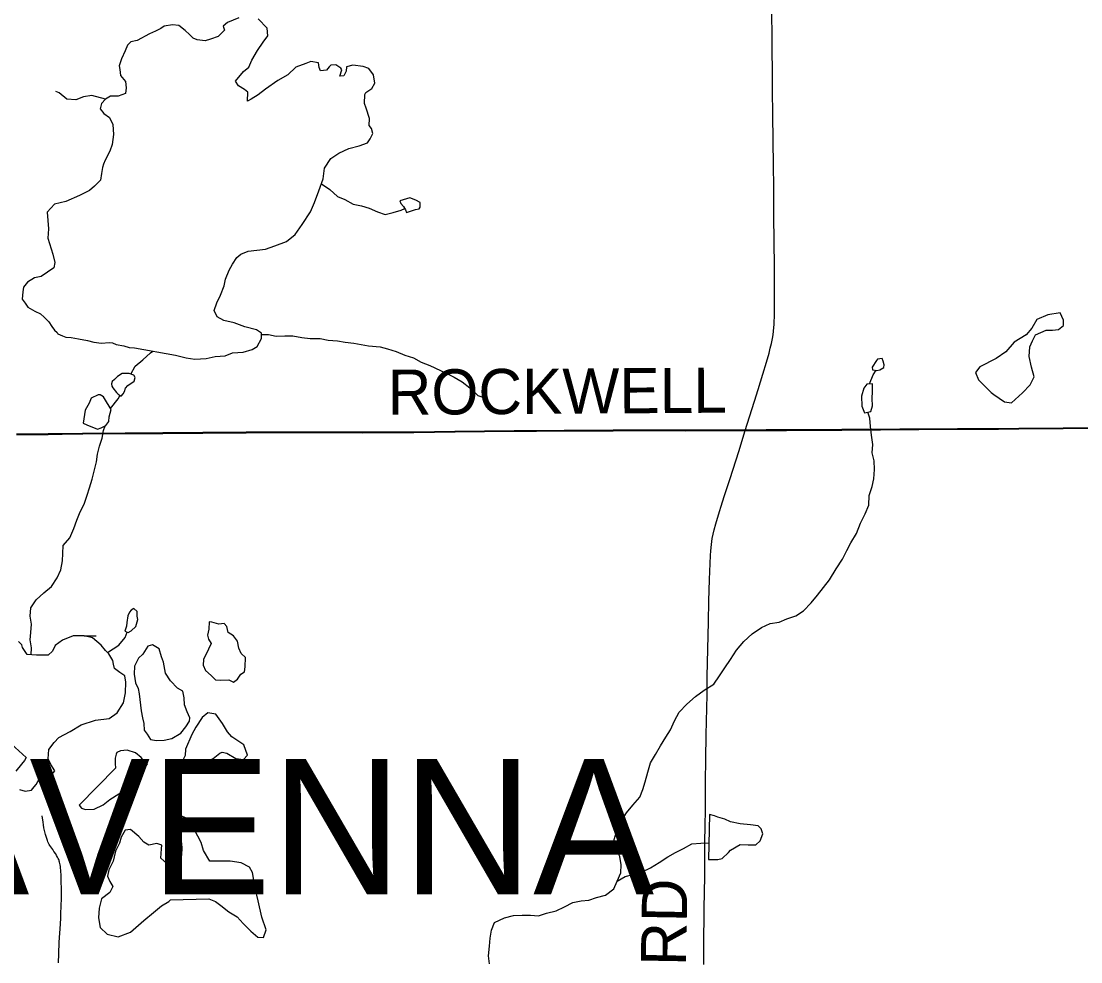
# Model space of a CAD drawing. Extents: x 0 to 34, y 0 to 22.
# Drawn here: x 14.299 to 15.63, y 14.945 to 16.128 of the extents above; entities that cross this region are included whole.
import ezdxf

# ---------------------------------------------------------------- set-up
doc = ezdxf.new("R2010")
doc.units = 0
for name, color, linetype in [('GM_X_Corporation', 7, 'Continuous'), ('GM_X_County_Road', 7, 'Continuous'), ('GM_X_County_Road_Text', 7, 'Continuous'), ('GM_X_Minor_Lake', 7, 'Continuous'), ('GM_X_Minor_River', 7, 'Continuous'), ('GM_X_Township_Road', 7, 'Continuous'), ('GM_X_Township_Text', 7, 'Continuous')]:
    doc.layers.add(name, color=color, linetype=linetype)

msp = doc.modelspace()

# ---------------------------------------------------------------- linework, layer by layer
at = {"layer": 'GM_X_Corporation'}
for points in [[(15.7195, 15.617), (15.5524, 15.6155), (15.5269, 15.6153), (15.4753, 15.6152), (15.3299, 15.6141), (15.3088, 15.6139), (15.2827, 15.614), (15.2604, 15.6138), (15.235, 15.6138), (15.2084, 15.6136), (15.172, 15.6134), (15.1329, 15.6134), (15.118, 15.6134), (15.0752, 15.6136), (15.0424, 15.6134), (14.9809, 15.6131), (14.9461, 15.6128), (14.9181, 15.6126), (14.8436, 15.6117), (14.792, 15.6111), (14.7634, 15.611), (14.7274, 15.6109), (14.7019, 15.6109), (14.6523, 15.6109), (14.6393, 15.6109), (14.6208, 15.611), (14.5813, 15.6109), (14.5268, 15.6104), (14.492, 15.61), (14.4765, 15.6099), (14.4473, 15.6097), (14.4292, 15.6096), (14.3758, 15.6093), (14.3497, 15.6089), (14.3323, 15.6087), (14.2926, 15.6084)], [(14.2926, 15.6084), (14.3323, 15.6087), (14.3497, 15.6089), (14.3758, 15.6093), (14.4292, 15.6096), (14.4473, 15.6097), (14.4765, 15.6099), (14.492, 15.61), (14.5268, 15.6104), (14.5813, 15.6109), (14.6208, 15.611), (14.6393, 15.6109), (14.6523, 15.6109), (14.7019, 15.6109), (14.7274, 15.6109), (14.7634, 15.611), (14.792, 15.6111), (14.8436, 15.6117), (14.9181, 15.6126), (14.9461, 15.6128), (14.9809, 15.6131), (15.0424, 15.6134), (15.0752, 15.6136), (15.118, 15.6134), (15.1329, 15.6134), (15.172, 15.6134), (15.2084, 15.6136), (15.235, 15.6138), (15.2604, 15.6138), (15.2827, 15.614), (15.3088, 15.6139), (15.3299, 15.6141), (15.4753, 15.6152), (15.5269, 15.6153), (15.5524, 15.6155), (15.7195, 15.617)]]:
    msp.add_lwpolyline(points, dxfattribs=at)
at = {"layer": 'GM_X_County_Road'}
for points in [[(15.2086, 15.6131), (15.2141, 15.6303), (15.2203, 15.6499), (15.2248, 15.6645), (15.2308, 15.6839), (15.2353, 15.6991), (15.2385, 15.7103), (15.2401, 15.7164), (15.2416, 15.7225), (15.2428, 15.7288), (15.2435, 15.7334), (15.2441, 15.738), (15.2446, 15.7426), (15.2448, 15.7465), (15.2453, 15.7598), (15.2454, 15.7669), (15.2454, 15.7757), (15.2454, 15.7911), (15.2453, 15.8193), (15.2445, 15.8826), (15.2444, 15.9209), (15.2441, 15.9449), (15.2436, 15.9788), (15.2433, 16.0086), (15.2431, 16.0193), (15.243, 16.0319), (15.2427, 16.0626), (15.2425, 16.0936), (15.242, 16.153)], [(14.2928, 15.6079), (14.3325, 15.6082), (14.3499, 15.6084), (14.376, 15.6087), (14.4295, 15.6091), (14.4475, 15.6092), (14.4767, 15.6094), (14.4922, 15.6095), (14.527, 15.6098), (14.5815, 15.6103), (14.621, 15.6104), (14.6395, 15.6104), (14.6525, 15.6104), (14.7021, 15.6104), (14.7276, 15.6103), (14.7636, 15.6104), (14.7922, 15.6105), (14.8438, 15.6112), (14.9183, 15.612), (14.9463, 15.6122), (14.9811, 15.6125), (15.0426, 15.6128), (15.0754, 15.613), (15.1182, 15.6129), (15.1331, 15.6128), (15.1722, 15.6129), (15.2086, 15.6131)], [(15.1564, 14.9415), (15.1565, 14.9632), (15.1571, 15.0123), (15.1576, 15.0521), (15.1578, 15.0806), (15.1579, 15.0931), (15.1584, 15.1179), (15.1585, 15.134), (15.1585, 15.152), (15.1586, 15.1632), (15.1588, 15.1713), (15.159, 15.1998), (15.1596, 15.2303), (15.1606, 15.2806), (15.1609, 15.3038), (15.1625, 15.3723), (15.163, 15.3983), (15.1637, 15.4256), (15.1645, 15.4456), (15.165, 15.456), (15.1655, 15.4618), (15.1662, 15.4695), (15.1672, 15.4772), (15.1683, 15.4828), (15.1695, 15.488), (15.1717, 15.4957), (15.1763, 15.5112), (15.1783, 15.5177), (15.1822, 15.5301), (15.1895, 15.5525), (15.2006, 15.5868), (15.2086, 15.6131)], [(15.2086, 15.6131), (15.2352, 15.6132), (15.2606, 15.6132), (15.2829, 15.6134), (15.309, 15.6134), (15.3301, 15.6135), (15.4755, 15.6146), (15.5271, 15.6148), (15.5526, 15.615), (15.7197, 15.6165), (15.7905, 15.6172), (15.849, 15.6177), (16.0069, 15.6183)]]:
    msp.add_lwpolyline(points, dxfattribs=at)
at = {"layer": 'GM_X_Minor_Lake'}
for p, q in [((14.7827, 15.887), (14.794, 15.8908)), ((14.4411, 15.7171), (14.4923, 15.7076)), ((15.3734, 15.7011), (15.3682, 15.6927)), ((15.5016, 15.6766), (15.5176, 15.6608)), ((15.5176, 15.6608), (15.5023, 15.6763)), ((14.4136, 15.6668), (14.4182, 15.6609)), ((15.3545, 15.6562), (15.3552, 15.6437)), ((14.381, 15.6203), (14.3946, 15.6147)), ((14.4324, 15.3799), (14.4313, 15.3715)), ((14.5338, 15.3382), (14.5275, 15.3249)), ((14.4468, 15.2818), (14.4493, 15.2606)), ((14.3458, 15.2268), (14.3601, 15.2345)), ((14.5131, 15.2307), (14.5049, 15.2125)), ((14.4375, 15.1638), (14.4573, 15.1939)), ((15.1637, 15.1303), (15.1623, 15.0734)), ((14.4863, 15.0227), (14.5344, 15.0242))]:
    msp.add_line(p, q, dxfattribs=at)
for points in [[(14.4923, 15.7076), (14.5059, 15.7043), (14.5169, 15.7029), (14.5309, 15.7034), (14.5423, 15.7061), (14.5548, 15.707), (14.5642, 15.7108), (14.5774, 15.7117), (14.5888, 15.7148), (14.5952, 15.7187), (14.6004, 15.7286), (14.6007, 15.7354), (14.5942, 15.7395), (14.5798, 15.7432), (14.5662, 15.7484), (14.5533, 15.7513), (14.5449, 15.7558), (14.5411, 15.7641), (14.5444, 15.7736), (14.5492, 15.7832), (14.5537, 15.7949), (14.5555, 15.8033), (14.56, 15.8147), (14.5641, 15.822), (14.5697, 15.8307), (14.5746, 15.8349), (14.584, 15.8384), (14.6056, 15.8412), (14.6173, 15.8451), (14.632, 15.8505), (14.6429, 15.8597), (14.6519, 15.8719), (14.662, 15.8879), (14.6672, 15.8997), (14.6727, 15.9146), (14.6779, 15.9294), (14.6797, 15.9431), (14.6879, 15.9549), (14.6977, 15.9618), (14.7102, 15.9676), (14.7234, 15.9711), (14.7336, 15.9746), (14.7373, 15.9799), (14.7407, 15.9864), (14.7387, 15.9928), (14.7361, 15.9966), (14.7364, 16.0053), (14.7321, 16.0182), (14.7302, 16.0242), (14.7305, 16.0356), (14.7316, 16.0379), (14.7391, 16.0429), (14.7432, 16.0497), (14.7412, 16.0603), (14.7355, 16.0683), (14.7283, 16.0709), (14.7154, 16.0723), (14.7075, 16.0703), (14.7068, 16.065), (14.7042, 16.0589), (14.6989, 16.0585), (14.7015, 16.0665), (14.7003, 16.0688), (14.6942, 16.0729), (14.6878, 16.0725), (14.6855, 16.0705), (14.6822, 16.0663), (14.6746, 16.0655), (14.673, 16.0697), (14.6722, 16.0754), (14.6624, 16.0772), (14.6564, 16.0745), (14.6439, 16.0698), (14.6338, 16.0603), (14.6209, 16.053), (14.6055, 16.0422), (14.5965, 16.0353), (14.5878, 16.0296), (14.5829, 16.0273), (14.5832, 16.0387), (14.5794, 16.042), (14.5718, 16.0465), (14.568, 16.0522), (14.5781, 16.0644), (14.5845, 16.0701), (14.5886, 16.0789), (14.5957, 16.0911), (14.6028, 16.1014), (14.6084, 16.1094), (14.6076, 16.1189), (14.5965, 16.1309)], [(14.5723, 16.1319), (14.5579, 16.1261), (14.5523, 16.1215), (14.5542, 16.1166), (14.546, 16.1085), (14.5365, 16.1051), (14.5297, 16.1031), (14.5199, 16.1045), (14.5149, 16.1064)], [(14.5149, 16.1064), (14.51, 16.1109), (14.5046, 16.1162), (14.4966, 16.1222), (14.4887, 16.1233), (14.4781, 16.1217), (14.474, 16.1186), (14.4672, 16.1151), (14.46, 16.1117), (14.4442, 16.1036), (14.4362, 16.1016), (14.4321, 16.0974), (14.4291, 16.0906), (14.4247, 16.0803), (14.4217, 16.0716), (14.4225, 16.067), (14.4233, 16.0594), (14.4298, 16.0519), (14.4306, 16.0439), (14.4296, 16.0367), (14.4205, 16.0336), (14.411, 16.0336), (14.4046, 16.0297), (14.3994, 16.0244), (14.3979, 16.0175), (14.4025, 16.0115), (14.4097, 16.0066), (14.4136, 15.9979), (14.4144, 15.9854), (14.413, 15.9725), (14.4101, 15.9641), (14.4041, 15.9531), (14.4019, 15.9481), (14.4008, 15.9436), (14.3993, 15.9364), (14.3982, 15.928), (14.3907, 15.9204), (14.3843, 15.915), (14.3719, 15.9085), (14.3545, 15.9008), (14.3406, 15.8976), (14.3312, 15.8877), (14.3329, 15.8665), (14.3322, 15.8551), (14.3384, 15.8346), (14.3408, 15.8244), (14.3397, 15.8176), (14.3235, 15.8068), (14.3152, 15.8049), (14.3065, 15.7995), (14.3013, 15.7934), (14.3006, 15.7873), (14.2999, 15.7782), (14.3037, 15.7733), (14.3068, 15.768), (14.3155, 15.7632), (14.3227, 15.7598), (14.3273, 15.7557), (14.3334, 15.7497), (14.3372, 15.744), (14.3403, 15.7391), (14.3437, 15.7361), (14.3445, 15.7346), (14.3506, 15.732), (14.3547, 15.7305), (14.3612, 15.7298), (14.3706, 15.7283), (14.382, 15.7261), (14.39, 15.7243), (14.3995, 15.7228), (14.4093, 15.7237), (14.4131, 15.7233), (14.418, 15.7211), (14.4275, 15.7193), (14.4343, 15.7174), (14.4411, 15.7171)], [(14.794, 15.8908), (14.7986, 15.8916), (14.8001, 15.8939), (14.8, 15.8996), (14.7947, 15.9026), (14.7871, 15.9056), (14.7746, 15.9017), (14.7758, 15.8983), (14.7792, 15.8949), (14.7815, 15.8907), (14.7827, 15.887)], [(15.6042, 15.7612), (15.5887, 15.7585), (15.5751, 15.7527), (15.5688, 15.7416), (15.5617, 15.7332), (15.5466, 15.724), (15.5361, 15.7118), (15.5241, 15.7037), (15.5033, 15.693), (15.4981, 15.6861), (15.5016, 15.6766)], [(15.5176, 15.6608), (15.521, 15.6582), (15.5343, 15.6492), (15.5434, 15.6478), (15.5569, 15.6604), (15.5667, 15.6703), (15.5719, 15.6806), (15.5684, 15.6927), (15.5653, 15.706), (15.5663, 15.7181), (15.5697, 15.7257), (15.5734, 15.7333), (15.587, 15.7391), (15.5949, 15.7392), (15.6021, 15.74), (15.6085, 15.745), (15.6085, 15.7518), (15.6042, 15.7612), (15.5887, 15.7585), (15.5751, 15.7527), (15.5688, 15.7416), (15.5617, 15.7332), (15.5466, 15.724), (15.5361, 15.7118), (15.5241, 15.7037), (15.5033, 15.693), (15.4981, 15.6861), (15.5016, 15.6766)], [(15.5176, 15.6608), (15.521, 15.6582), (15.5343, 15.6492), (15.5434, 15.6478), (15.5569, 15.6604), (15.5667, 15.6703), (15.5719, 15.6806), (15.5684, 15.6927), (15.5653, 15.706), (15.5663, 15.7181), (15.5697, 15.7257), (15.5734, 15.7333), (15.587, 15.7391), (15.5949, 15.7392), (15.6021, 15.74), (15.6085, 15.745), (15.6085, 15.7518), (15.6042, 15.7612)], [(15.3682, 15.6927), (15.3686, 15.6893), (15.3739, 15.6886), (15.3777, 15.6894), (15.3826, 15.6924), (15.3833, 15.6958), (15.3818, 15.7004), (15.3806, 15.7034), (15.3749, 15.7026), (15.3734, 15.7011)], [(14.4182, 15.6609), (14.4204, 15.6589), (14.4242, 15.6563), (14.4268, 15.659), (14.4283, 15.662), (14.4298, 15.6662), (14.4324, 15.6696), (14.4407, 15.675), (14.4418, 15.6796), (14.4403, 15.6826), (14.4342, 15.6848), (14.4255, 15.6847), (14.4195, 15.6809), (14.4157, 15.6771), (14.4127, 15.6748), (14.412, 15.6717), (14.4124, 15.6687), (14.4136, 15.6668)], [(15.3552, 15.6437), (15.3584, 15.6354), (15.3664, 15.6369), (15.3686, 15.6442), (15.3681, 15.6532), (15.3684, 15.662), (15.3684, 15.6718), (15.3616, 15.6714), (15.3578, 15.6664), (15.3545, 15.6562)], [(14.3946, 15.6147), (14.3992, 15.6163), (14.4048, 15.6194), (14.4085, 15.6243), (14.4093, 15.6304), (14.4104, 15.6349), (14.4115, 15.6395), (14.4092, 15.6437), (14.4057, 15.6489), (14.4019, 15.6554), (14.3977, 15.658), (14.3954, 15.658), (14.3867, 15.6537), (14.3841, 15.6473), (14.3789, 15.6385), (14.3764, 15.6222), (14.381, 15.6203)], [(14.4313, 15.3715), (14.431, 15.367), (14.4288, 15.3609), (14.433, 15.359), (14.4367, 15.3613), (14.4427, 15.3667), (14.4453, 15.3754), (14.4445, 15.3796), (14.4445, 15.3853), (14.4403, 15.3891), (14.4369, 15.3871), (14.4347, 15.3845), (14.4324, 15.3799)], [(14.5275, 15.3249), (14.5271, 15.3181), (14.5302, 15.3112), (14.5375, 15.3049), (14.5428, 15.2996), (14.5492, 15.2989), (14.5595, 15.2997), (14.5652, 15.2967), (14.5704, 15.3002), (14.5745, 15.3067), (14.5791, 15.3097), (14.5801, 15.3158), (14.5804, 15.3276), (14.5751, 15.3324), (14.572, 15.3392), (14.5704, 15.3483), (14.5655, 15.3547), (14.5586, 15.3592), (14.557, 15.3664), (14.5536, 15.3702), (14.5468, 15.3694), (14.5381, 15.372), (14.5347, 15.3723), (14.5344, 15.3632), (14.5325, 15.3556), (14.5341, 15.3507), (14.5375, 15.3451), (14.5338, 15.3382)], [(14.3601, 15.2345), (14.3741, 15.2429), (14.3918, 15.2488), (14.4092, 15.2508), (14.419, 15.2581), (14.4272, 15.2706), (14.4298, 15.2832), (14.43, 15.2965), (14.4288, 15.3044), (14.4224, 15.3089), (14.4159, 15.3138), (14.4147, 15.3191), (14.4136, 15.324), (14.4089, 15.3323), (14.4044, 15.3365), (14.399, 15.3429), (14.388, 15.3523), (14.3777, 15.3548), (14.3637, 15.3547), (14.3505, 15.3493), (14.3411, 15.3428), (14.3378, 15.3356), (14.3325, 15.3306), (14.3177, 15.3305), (14.306, 15.3315), (14.3003, 15.3402), (14.2995, 15.3436), (14.2953, 15.3478)], [(14.4493, 15.2606), (14.4512, 15.2519), (14.4528, 15.2447), (14.4532, 15.2363), (14.4567, 15.2311), (14.4609, 15.2246), (14.4685, 15.2232), (14.4783, 15.2236), (14.4878, 15.2256), (14.4991, 15.2325), (14.5054, 15.2405), (14.5099, 15.2474), (14.5106, 15.2516), (14.5072, 15.2591), (14.5037, 15.2682), (14.5032, 15.2769), (14.5017, 15.2852), (14.4948, 15.289), (14.4864, 15.2984), (14.4799, 15.3078), (14.4772, 15.3215), (14.4748, 15.3283), (14.4721, 15.3385), (14.4634, 15.3434), (14.4577, 15.3418), (14.4513, 15.3319), (14.4461, 15.3269), (14.4409, 15.3166), (14.4406, 15.3068), (14.4422, 15.2958), (14.4456, 15.2886), (14.4468, 15.2818)], [(14.5049, 15.2125), (14.5046, 15.2045), (14.5012, 15.1976), (14.5062, 15.1916), (14.5172, 15.1917), (14.527, 15.1944), (14.5398, 15.2006), (14.5481, 15.2071), (14.5511, 15.2086), (14.5572, 15.2072), (14.5682, 15.2004), (14.578, 15.1994), (14.5829, 15.2047), (14.5783, 15.2176), (14.5634, 15.2277), (14.5577, 15.2341), (14.5516, 15.2447), (14.5431, 15.2564), (14.5333, 15.2582), (14.5261, 15.2521), (14.5179, 15.2399), (14.5131, 15.2307)], [(14.2964, 15.1616), (14.3036, 15.1594), (14.3115, 15.1606), (14.3149, 15.1651), (14.3175, 15.1678), (14.3216, 15.1754), (14.3204, 15.1811), (14.3208, 15.186), (14.3337, 15.1778), (14.3393, 15.1831), (14.3408, 15.185), (14.3359, 15.193), (14.3324, 15.2001), (14.3334, 15.2119), (14.3398, 15.2207), (14.3458, 15.2268)], [(14.2865, 15.2188), (14.3048, 15.2018), (14.3029, 15.198), (14.2988, 15.1934), (14.2916, 15.1847)], [(14.4573, 15.1939), (14.4535, 15.1965), (14.4493, 15.2018), (14.4421, 15.2078), (14.4319, 15.2111), (14.4232, 15.2103), (14.4186, 15.208), (14.4179, 15.2061), (14.4168, 15.2008), (14.4165, 15.1943), (14.4169, 15.1883), (14.3715, 15.1417), (14.3745, 15.1383), (14.3795, 15.1364), (14.3904, 15.1369), (14.4014, 15.1423), (14.41, 15.1488), (14.4213, 15.1561), (14.4292, 15.1599), (14.4375, 15.1638)], [(14.5344, 15.0242), (14.5427, 15.0209), (14.5496, 15.0156), (14.5595, 15.0077), (14.5698, 15.0014), (14.5774, 14.9931), (14.5873, 14.9833), (14.5961, 14.9758), (14.6029, 14.9755), (14.6066, 14.985), (14.6008, 15.0009), (14.5965, 15.0217), (14.5926, 15.0376), (14.5894, 15.0573), (14.5855, 15.0641), (14.5749, 15.0693), (14.5613, 15.0715), (14.551, 15.0714), (14.5355, 15.0716), (14.5275, 15.0849), (14.5247, 15.0951), (14.5163, 15.1109), (14.5109, 15.1192), (14.5052, 15.126), (14.4968, 15.1297), (14.492, 15.1244), (14.4951, 15.113), (14.499, 15.1006), (14.5006, 15.0888), (14.4999, 15.079), (14.4943, 15.0725), (14.4814, 15.0686), (14.4742, 15.0753), (14.4748, 15.0871), (14.4752, 15.0917), (14.4691, 15.0935), (14.4589, 15.0915), (14.4528, 15.0953), (14.4463, 15.1024), (14.436, 15.1111), (14.4292, 15.1103), (14.4244, 15.1015), (14.4222, 15.0943), (14.417, 15.084), (14.4155, 15.0768), (14.414, 15.0715), (14.4088, 15.0604), (14.407, 15.0525), (14.4101, 15.046), (14.4139, 15.0396), (14.4098, 15.032), (14.3993, 15.0243), (14.3967, 15.0122), (14.3957, 15), (14.398, 14.9879), (14.4064, 14.9797), (14.4205, 14.9763), (14.4359, 14.9822), (14.4528, 14.9967), (14.4649, 15.007), (14.475, 15.0154), (14.4841, 15.0208), (14.4863, 15.0227)], [(15.1623, 15.0734), (15.174, 15.0735), (15.1797, 15.075), (15.1875, 15.0823), (15.1902, 15.0854), (15.2022, 15.0923), (15.2124, 15.092), (15.2219, 15.0921), (15.2272, 15.097), (15.2305, 15.1058), (15.2286, 15.1122), (15.2247, 15.116), (15.2153, 15.117), (15.202, 15.1184), (15.1899, 15.121), (15.1831, 15.1244), (15.1743, 15.127), (15.1698, 15.1284), (15.1637, 15.1303)]]:
    msp.add_lwpolyline(points, dxfattribs=at)
at = {"layer": 'GM_X_Minor_River'}
for points in [[(14.4046, 16.0297), (14.3872, 16.0345), (14.377, 16.0325), (14.3672, 16.029), (14.3558, 16.0297), (14.3463, 16.0376), (14.3421, 16.0395)], [(14.6758, 15.9233), (14.6863, 15.9162), (14.6959, 15.9072), (14.7054, 15.9034), (14.716, 15.8978), (14.7262, 15.8956), (14.7361, 15.8927), (14.7464, 15.8882), (14.7562, 15.8845), (14.7661, 15.8872), (14.7763, 15.8899), (14.7809, 15.892)], [(14.6006, 15.7338), (14.6094, 15.7336), (14.6189, 15.7317), (14.6299, 15.7322), (14.6401, 15.7319), (14.6511, 15.7301), (14.6617, 15.7286), (14.6742, 15.7287), (14.6844, 15.7265), (14.6962, 15.7259), (14.7056, 15.724), (14.7166, 15.723), (14.7352, 15.7193), (14.7496, 15.7183), (14.7591, 15.7157), (14.7697, 15.7124), (14.7807, 15.7079), (14.7917, 15.7046), (14.8012, 15.699), (14.8122, 15.6949), (14.8327, 15.6852), (14.8426, 15.6803), (14.8529, 15.6744), (14.8624, 15.6668), (14.8723, 15.6571), (14.8788, 15.6548)], [(14.4363, 15.684), (14.4417, 15.694), (14.4515, 15.702), (14.4612, 15.7108), (14.4638, 15.7129)], [(15.3646, 15.6716), (15.3694, 15.6829), (15.3732, 15.6887)], [(14.4108, 15.6406), (14.4204, 15.6528), (14.4228, 15.6573)], [(15.1459, 15.2784), (15.1568, 15.2865), (15.1692, 15.2941), (15.1763, 15.3044), (15.1831, 15.3147), (15.1902, 15.325), (15.1976, 15.3368), (15.207, 15.3475), (15.2172, 15.3574), (15.2292, 15.3651), (15.2398, 15.3705), (15.2511, 15.3721), (15.2609, 15.3764), (15.2722, 15.3799), (15.282, 15.3864), (15.2914, 15.3963), (15.2993, 15.4059), (15.3068, 15.4158), (15.3143, 15.4253), (15.3229, 15.439), (15.3307, 15.4512), (15.3363, 15.4623), (15.3412, 15.4718), (15.3483, 15.4836), (15.3535, 15.4965), (15.3594, 15.5083), (15.3639, 15.5193), (15.3645, 15.5311), (15.3679, 15.5425), (15.3701, 15.5524), (15.3711, 15.5638), (15.3706, 15.5748), (15.3683, 15.585), (15.369, 15.5956), (15.3674, 15.607), (15.3661, 15.618), (15.3653, 15.6286), (15.3627, 15.6362)], [(14.311, 15.3311), (14.3116, 15.3399), (14.31, 15.3498), (14.3107, 15.3592), (14.3114, 15.3695), (14.3098, 15.3797), (14.3105, 15.39), (14.3172, 15.4003), (14.327, 15.4087), (14.3368, 15.4167), (14.3439, 15.4278), (14.3483, 15.438), (14.3505, 15.449), (14.3508, 15.4585), (14.3511, 15.4684), (14.3597, 15.4779), (14.3649, 15.4897), (14.3683, 15.5004), (14.3727, 15.5107), (14.3776, 15.5205), (14.3813, 15.5316), (14.3842, 15.5411), (14.3879, 15.5517), (14.3931, 15.5738), (14.3945, 15.5832), (14.3971, 15.5935), (14.4004, 15.6034), (14.4018, 15.6129), (14.4041, 15.619)], [(14.4072, 15.3339), (14.4213, 15.343), (14.4292, 15.3526), (14.4318, 15.3595)], [(14.3777, 15.3548), (14.3929, 15.3549)], [(14.887, 14.9424), (14.8858, 14.9526), (14.8872, 14.9644), (14.8879, 14.9746), (14.8897, 14.9849), (14.8934, 14.9944), (14.9062, 15.0002), (14.9172, 15.0033), (14.9282, 15.0037), (14.9388, 15.0034), (14.9486, 15.0028), (14.9588, 15.0059), (14.9709, 15.009), (14.9814, 15.014), (14.992, 15.0194), (15.0022, 15.0214), (15.012, 15.0226), (15.0218, 15.0257), (15.0328, 15.0288), (15.0433, 15.0368), (15.0478, 15.0464), (15.0523, 15.057), (15.0526, 15.0669), (15.051, 15.0775), (15.046, 15.0873), (15.044, 15.0987), (15.0477, 15.1108), (15.0521, 15.1211), (15.0592, 15.1321), (15.0671, 15.1417), (15.0761, 15.152), (15.0798, 15.1615), (15.0828, 15.1714), (15.0861, 15.1832), (15.0894, 15.1953), (15.0957, 15.2056), (15.1021, 15.2163), (15.1088, 15.2273), (15.1148, 15.2368), (15.1196, 15.2479), (15.1256, 15.2589), (15.135, 15.2688), (15.1459, 15.2784)], [(15.0478, 15.0464), (15.0576, 15.0521), (15.0674, 15.0548), (15.0784, 15.0576), (15.0893, 15.063), (15.1006, 15.0699), (15.1111, 15.0768), (15.1209, 15.0822), (15.1311, 15.0872), (15.1413, 15.0933), (15.1526, 15.0942), (15.1628, 15.0947)]]:
    msp.add_lwpolyline(points, dxfattribs=at)
at = {"layer": 'GM_X_Township_Road'}
msp.add_lwpolyline([(14.3455, 14.9437), (14.3459, 14.9548), (14.3464, 14.9694), (14.3478, 14.9923), (14.3482, 15.0001), (14.3485, 15.0071), (14.3488, 15.0138), (14.349, 15.0264), (14.349, 15.0394), (14.3489, 15.043), (14.3488, 15.0501), (14.3487, 15.0517), (14.3487, 15.0537), (14.3486, 15.0552), (14.3484, 15.0576), (14.3482, 15.0607), (14.3481, 15.0622), (14.3479, 15.0637), (14.3478, 15.0647), (14.3475, 15.0668), (14.3471, 15.0687), (14.3468, 15.0702), (14.3464, 15.0713), (14.3461, 15.0724), (14.3457, 15.0734), (14.3451, 15.0749), (14.3442, 15.0765), (14.3431, 15.0785), (14.3419, 15.0805), (14.3396, 15.0838), (14.3382, 15.086), (14.3369, 15.0879), (14.3357, 15.0896), (14.3347, 15.0911), (14.3338, 15.0926), (14.3334, 15.0931), (14.333, 15.0941), (14.3325, 15.095), (14.3321, 15.0959), (14.3315, 15.0974), (14.3307, 15.0998), (14.3289, 15.1052), (14.3281, 15.1083), (14.3271, 15.1132), (14.3265, 15.117), (14.326, 15.1204), (14.3251, 15.1283)], dxfattribs=at)

# ---------------------------------------------------------------- texts
at = {"layer": 'GM_X_County_Road_Text'}
for s, rotation, p in [('ROCKWELL', 0.3709, (14.7594, 15.6327)), ('RD', 89.0138, (15.1341, 14.9393))]:
    msp.add_text(s, height=0.05682, rotation=rotation, dxfattribs=at).set_placement(p)
at = {"layer": 'GM_X_Township_Text'}
msp.add_text('RAVENNA', height=0.17045, rotation=0, dxfattribs=at).set_placement((13.9921, 15.0296))

doc.saveas('drawing.dxf')
